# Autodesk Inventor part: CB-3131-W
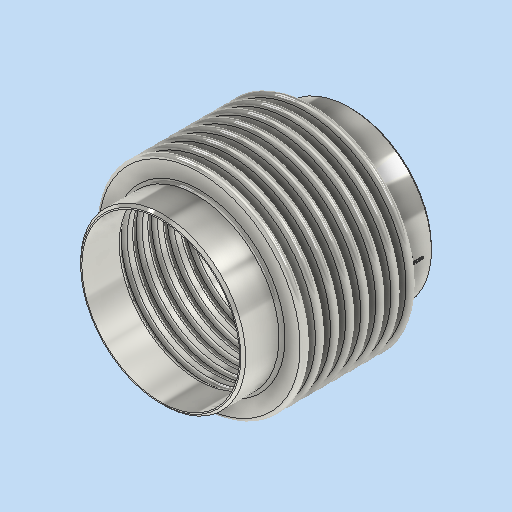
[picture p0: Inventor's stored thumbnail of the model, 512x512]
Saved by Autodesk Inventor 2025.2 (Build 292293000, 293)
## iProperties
Company: DN.RU
Created: 2026-04
Part Number: CB-3131-W
Material: Типовые
Document SubType Name: Modeling
Designer: DN.RU
Density: 4.61017 g/cm^3
Appearance: По умолчанию
Description: D140-02128
Mass: 12600 g
Surface Area: 15581.6 cm^2
Volume: 2733.09 cm^3
Author: DN.RU
Title: Компенсатор сильфонный осевой DN.ru Ду250 Ру16
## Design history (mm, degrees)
sketch "Эскиз1"
  geometry: L1 (0, 0)-(0, -157.5); L2 (136.5, -157.5)-(136.5, 0); L3 (136.5, 0)-(0, 0); L4 (136.5, 0)-(136.5, -12.5); L5 (106.5, -12.5)-(166.5, -12.5); L6 (106.5, -18.5)-(166.5, -18.5); L7 (166.5, -6.5)-(106.5, -6.5); L8 (166.5, -15.5)-(106.5, -15.5); L9 (106.5, -9.5)-(166.5, -9.5); L10 (166.5, -31.5)-(106.5, -31.5); L11 (106.5, -34.5)-(166.5, -34.5); L12 (106.5, -37.5)-(166.5, -37.5); L13 (106.5, -43.5)-(166.5, -43.5); L14 (166.5, -40.5)-(106.5, -40.5); L15 (166.5, -56.5)-(106.5, -56.5); L16 (106.5, -59.5)-(166.5, -59.5); L17 (106.5, -62.5)-(166.5, -62.5); L18 (106.5, -68.5)-(166.5, -68.5); L19 (166.5, -65.5)-(106.5, -65.5); L20 (166.5, -81.5)-(106.5, -81.5); L21 (106.5, -84.5)-(166.5, -84.5); L22 (106.5, -87.5)-(166.5, -87.5); L23 (106.5, -93.5)-(166.5, -93.5); L24 (166.5, -90.5)-(106.5, -90.5); L25 (0, -157.5)-(136.5, -157.5); L26 (136.5, -157.5)-(130.5, -157.5); L27 (136.5, -81.5)-(133.5, -81.5); L28 (130.5, -157.5)-(130.5, -90.5); L29 (136.5, -84.5)-(133.5, -84.5); L30 (133.5, -84.5)-(133.5, -65.5); L31 (136.5, -59.5)-(133.5, -59.5); L32 (133.5, -59.5)-(133.5, -40.5); L33 (136.5, -34.5)-(133.5, -34.5); L34 (133.5, -34.5)-(133.5, -15.5); L35 (136.5, -9.5)-(133.5, -9.5); L36 (133.5, -9.5)-(133.5, 0); A1 r 6 centre (106.5, -12.5) between (106.5, -6.5) and (106.5, -18.5); A2 r 6 centre (166.5, -12.5) between (166.5, -18.5) and (166.5, -6.5); A3 r 3 centre (106.5, -12.5) between (106.5, -9.5) and (106.5, -15.5); A4 r 3 centre (166.5, -12.5) between (166.5, -15.5) and (166.5, -9.5); A5 r 3 centre (106.5, -37.5) between (106.5, -34.5) and (106.5, -40.5); A6 r 6 centre (106.5, -37.5) between (106.5, -31.5) and (106.5, -43.5); A7 r 3 centre (166.5, -37.5) between (166.5, -40.5) and (166.5, -34.5); A8 r 6 centre (166.5, -37.5) between (166.5, -43.5) and (166.5, -31.5); A9 r 3 centre (106.5, -62.5) between (106.5, -59.5) and (106.5, -65.5); A10 r 6 centre (106.5, -62.5) between (106.5, -56.5) and (106.5, -68.5); A11 r 3 centre (166.5, -62.5) between (166.5, -65.5) and (166.5, -59.5); A12 r 6 centre (166.5, -62.5) between (166.5, -68.5) and (166.5, -56.5); A13 r 3 centre (106.5, -87.5) between (106.5, -84.5) and (106.5, -90.5); A14 r 6 centre (106.5, -87.5) between (106.5, -81.5) and (106.5, -93.5); A15 r 3 centre (166.5, -87.5) between (166.5, -90.5) and (166.5, -84.5); A16 r 6 centre (166.5, -87.5) between (166.5, -93.5) and (166.5, -81.5); 18 further points
  constraints: 80 end point, 32 point on circle, 16 centre point, 15 point on line, 6 midpoint, 5 perpendicular, 4 tangent, 3 parallel, 2 vertical, 1 horizontal, 69 other
  dimensions: "d0" = 157.5 distance of L1.start L1.end; "d1" = 136.5 distance of L2.start L1.end; "d3" = 12.5 distance of L2.end L4.end; "d4" = 30 distance of L4.end L5.end; "d5" = 12 diameter of A2; "d6" = 3 distance between parallel lines of L6 L8; "d9" = 25 distance of L4.end point (136.5, -37.5); "d14" = 6 distance of L2.start L26.end; "d15" = 3 distance of L27.start L27.end; "d16" = 3 distance of L29.start L29.end; "d17" = 3 distance of L31.start L31.end; "d18" = 3 distance of L33.start L33.end; "d19" = 3 distance of L35.start L35.end
revolve "Вращение1" sketch "Эскиз1" stored, may be unused: angle "d20" = 360 deg
mirror "Зеркальное отражение1"
chamfer "Фаска1" distance "d21" = 4; stored, may be unused: second distance "d22" = 2, angle "d23" = 45 deg
fillet "Сопряжение1" dims "d24" = 5
node "РабПлоскость1"
sketch "Эскиз2"
  geometry: L1 (6.86, 23.005)-(6.86, -17.385); L2 (6.86, -17.385)-(-1.271, -17.385); L3 (-1.271, -17.385)-(-1.271, 23.005); L4 (-1.271, 23.005)-(6.86, 23.005); 1 further point
  constraints: 2 other
feature "Рельеф1" sketch "Эскиз2" dims "d25" = 0.1, "d26" = 0
node "Твердое тело1"
node "Эскиз — прямоугольный массив1" dims "d9" = 25, "d12" = 10
